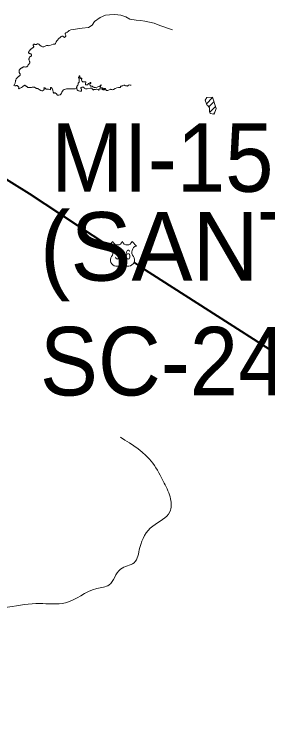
# Model space of a CAD drawing. Extents: x 553962 to 842807, y 8883888 to 9032388.
# Drawn here: x 598511 to 600358, y 8911220 to 8916501 of the extents above; entities that cross this region are included whole.
import ezdxf
from ezdxf.enums import TextEntityAlignment as Align

# ---------------------------------------------------------------- set-up
doc = ezdxf.new("R2010")
doc.units = 0
doc.header["$LTSCALE"] = 200
doc.layers.add('6', color=7, linetype='Continuous', lineweight=13)

msp = doc.modelspace()

# ---------------------------------------------------------------- linework, layer by layer
at = {"layer": '6'}
for p, q in [((599911.6, 8915849.7), (599957.3, 8915895.4)), ((599930.4, 8915826.1), (599967.3, 8915863)), ((599936, 8915789.3), (599977.2, 8915830.5)), ((599963, 8915773.8), (599972, 8915782.8)), ((599197.4, 8914812), (599229.4, 8914844)), ((599369.2, 8914844), (599401.2, 8914812))]:
    msp.add_line(p, q, dxfattribs=at)
at = {"layer": '6', "lineweight": 40}
for points in [[(596588.2, 8916457.2), (598619.5, 8915193.9), (599198.7, 8914813.4)], [(599384.5, 8914691.3), (599431.6, 8914660.4), (600961.1, 8913682.3), (601460.1, 8913331.7), (601690.5, 8912983.4), (601771, 8912890.8), (601830.7, 8912847.9), (601883.5, 8912819.1), (601916.8, 8912809.3)]]:
    msp.add_lwpolyline(points, dxfattribs=at)
at = {"layer": '6'}
for points in [[(599664, 8916389.5), (599573.3, 8916420.2), (599530.2, 8916437.2), (599461.5, 8916451.1), (599431.6, 8916456.9), (599399.5, 8916459.4), (599354, 8916466.4), (599323.1, 8916483.3), (599287.7, 8916495.8), (599244.5, 8916500.6), (599205.7, 8916498.8), (599176.8, 8916494.6), (599135.6, 8916479.4), (599094.3, 8916448.7), (599077.5, 8916423.3), (599051.8, 8916404.7), (599005.2, 8916401.8), (598921.8, 8916388.1), (598911.5, 8916383.7), (598902.3, 8916377.5), (598896.6, 8916370.4)], [(598896.6, 8916370.4), (598896.5, 8916370.3), (598893.5, 8916368.7), (598887.3, 8916366.8), (598882.2, 8916362.8), (598880.8, 8916359.9), (598881.9, 8916356.9), (598884.8, 8916351.1), (598886.9, 8916345), (598886.3, 8916341.8), (598884.8, 8916338.9), (598880.1, 8916334.3), (598877, 8916333.6), (598873.8, 8916334.3), (598868.3, 8916337.8), (598863.6, 8916342.2), (598860.4, 8916342.9), (598857.1, 8916342.3), (598851.2, 8916339.6), (598846.8, 8916334.9), (598841.8, 8916330.9), (598836.5, 8916327.1), (598819.4, 8916307.3), (598815.4, 8916302.1), (598813, 8916296.2), (598811.1, 8916289.8), (598809.4, 8916287.1), (598806.8, 8916285.3), (598793.8, 8916283.8), (598781.7, 8916278.8), (598769.7, 8916273.6), (598763.3, 8916273), (598756.9, 8916274.3)], [(598756.7, 8916274.4), (598751.2, 8916275.1), (598746, 8916273.7), (598736, 8916269.2), (598731.6, 8916266.1), (598726.3, 8916264.3), (598720.8, 8916264.1), (598715.4, 8916265), (598710.1, 8916266.6), (598705.4, 8916269.2), (598697.1, 8916276.4), (598689.5, 8916284.3), (598684.8, 8916287.2), (598682.1, 8916287.3), (598679.5, 8916286.3)], [(599008.9, 8915970.5), (599005.2, 8915971.1), (599001.8, 8915970.8), (598999, 8915968.7), (598996.6, 8915966.3), (598996.6, 8915962.6), (598998.2, 8915958.4), (599000.3, 8915955.5), (599001.3, 8915951.8), (599001.6, 8915948.2), (599001.1, 8915944.2), (599000.3, 8915942.6), (598996.1, 8915942.1), (598992.9, 8915942.1), (598988.2, 8915942.4), (598980.2, 8915944.2), (598973.4, 8915946.6), (598969.4, 8915950.7), (598967.1, 8915956.6), (598965.2, 8915970.8), (598965.5, 8915975.2), (598968.9, 8915978.4), (598971.6, 8915982.3), (598974.5, 8915987), (598975.3, 8915992.3), (598975.3, 8915995.2), (598975.5, 8915998.1), (598976.8, 8916000.4), (598980.5, 8916004.1), (598983.4, 8916008.3), (598983.4, 8916013.8), (598983.2, 8916023.6), (598982.9, 8916029.1), (598982.9, 8916032.5), (598981.6, 8916036.2), (598979, 8916039.9), (598981.8, 8916043.3), (598983.7, 8916049.1), (598985.3, 8916051.4), (598985.5, 8916054.1), (598987.1, 8916053.5), (598987.4, 8916050.1), (598987.7, 8916046.6), (598989.2, 8916043.5), (598993.2, 8916037), (598994.2, 8916034.6), (598996.6, 8916034.9), (598999, 8916036.4), (599001.1, 8916036.7), (599002.9, 8916034.1), (599001.3, 8916030.1), (599001.6, 8916025.9), (599001.6, 8916022), (599003.2, 8916017.2), (599005.3, 8916012.8), (599008.7, 8916010.4), (599011.8, 8916009.8)], [(599084.8, 8915949.4), (599084.9, 8915951), (599083.9, 8915953.7), (599079.6, 8915958), (599076.2, 8915963), (599073.6, 8915964.1), (599070.4, 8915964.2), (599064.2, 8915963), (599040.7, 8915959.1), (599028.6, 8915958.6), (599023.2, 8915961.1), (599019.1, 8915965.5), (599014.9, 8915969.5), (599008.8, 8915970.5), (599002.7, 8915971), (598997.7, 8915967.7), (598996.3, 8915965.3), (598996.7, 8915962.2), (598999.3, 8915956.9), (599001.4, 8915951.3), (599001.3, 8915945.3), (599000.2, 8915942.6), (598997.3, 8915942), (598991.2, 8915942.1), (598979.4, 8915944.4), (598973.7, 8915946.4), (598969.8, 8915950.1), (598967.4, 8915955.4), (598966.2, 8915961.8), (598965.5, 8915968.6), (598965.3, 8915974.9), (598969.6, 8915979.1), (598972.8, 8915984.2), (598975.1, 8915989.6), (598975.3, 8915995.6), (598975.7, 8915998.6), (598977.4, 8916001.1), (598981.7, 8916005.3), (598983.3, 8916007.9), (598983.7, 8916010.8), (598983.3, 8916016.9), (598982.9, 8916028.8), (598982.4, 8916034.8), (598978.9, 8916039.8), (598982.5, 8916044.6), (598983.1, 8916047.6), (598984.6, 8916050.1), (598985.2, 8916053.2), (598985.8, 8916054.1), (598987.3, 8916053.4), (598987.5, 8916047.2), (598993.2, 8916036.7), (598993.7, 8916035.1), (598994.8, 8916034.4), (598997.7, 8916035.6), (599000.4, 8916036.8), (599002.7, 8916035), (599002.3, 8916032.1), (599001.2, 8916029.3), (599001.6, 8916023.2), (599003.1, 8916017.5), (599005.8, 8916012.2), (599008.3, 8916010.6), (599011.3, 8916009.8), (599017.3, 8916009.3), (599029.2, 8916008.2), (599032, 8916006.7), (599032.1, 8916004), (599029.5, 8915998.4), (599028.7, 8915992.5), (599030.6, 8915990.1), (599033.2, 8915988.5), (599038.9, 8915986.9), (599045, 8915987.8), (599047.6, 8915989.5), (599049, 8915992.2), (599049.9, 8915995.1), (599052.1, 8915996.9), (599057.1, 8916000.2), (599062.8, 8916002.2), (599065.4, 8916003.5), (599068.2, 8916003.6), (599068.2, 8916000.4), (599067.4, 8915997.6), (599062.5, 8915994.1), (599062.3, 8915988.1), (599065, 8915982.7), (599069.2, 8915978.6), (599071.7, 8915976.9), (599074.9, 8915976.9), (599077.9, 8915976.9), (599079.8, 8915974.8), (599082.2, 8915973.6), (599085.4, 8915973.6), (599090.5, 8915970.2), (599093, 8915968.8)], [(599093, 8915968.8), (599096, 8915968.4), (599102, 8915968.8), (599113.8, 8915971.1), (599125.2, 8915974.7), (599130.8, 8915973.1), (599134.3, 8915973.4), (599135.2, 8915974), (599134.6, 8915975.3), (599134.3, 8915978.3), (599136.3, 8915980.6), (599138.7, 8915982.3), (599141.3, 8915983.6), (599141.8, 8915985), (599141.2, 8915986.4), (599141.1, 8915987.6), (599142.8, 8915987.7), (599144.3, 8915986.8), (599144.6, 8915985.5), (599142.6, 8915983.1), (599139.9, 8915977.8), (599139.2, 8915971.8), (599139.2, 8915968.8), (599141.3, 8915967), (599147.4, 8915966.3), (599150.5, 8915965.1), (599152.7, 8915963), (599152.8, 8915960), (599154.1, 8915959.1), (599155.8, 8915959.1), (599157.2, 8915961.6), (599159.7, 8915962.2), (599166.6, 8915960.2), (599172.6, 8915960.3), (599175.4, 8915959.6), (599177.1, 8915956.7), (599177, 8915955.3), (599175.6, 8915955.1), (599173.2, 8915956.8), (599167.2, 8915957.4), (599167, 8915955.9), (599168.3, 8915955.1), (599168.7, 8915953.8), (599167.5, 8915952.9), (599165.6, 8915950.8), (599162.7, 8915951.6), (599160.7, 8915953.8), (599159.3, 8915953.6), (599158.3, 8915952.4), (599155.8, 8915950.9), (599153.3, 8915952.5), (599147.8, 8915954.7), (599143.4, 8915958.7), (599137.4, 8915959.2), (599134.3, 8915959.1), (599132, 8915957.4), (599129.5, 8915955.8), (599127.7, 8915953.4), (599127.5, 8915947.2), (599127.1, 8915946.7), (599126.1, 8915947.5), (599123.5, 8915950.7), (599118.3, 8915953.7), (599112.6, 8915955.2), (599106.6, 8915954.9), (599103.8, 8915953.7), (599100.8, 8915953.5), (599094.9, 8915954.2), (599091.9, 8915954.2), (599089.1, 8915953.3), (599087.7, 8915950.6), (599084.9, 8915949.5)], [(599176.8, 8915955.2), (599177.7, 8915952.1), (599179.8, 8915949.5), (599182.3, 8915947.3), (599185.3, 8915946.2), (599191.9, 8915945.7), (599197.9, 8915948.5), (599209.9, 8915953.8), (599212.9, 8915955.1), (599216.1, 8915954.6), (599222.5, 8915953.2), (599228.9, 8915952.1), (599235.1, 8915954.3), (599246.6, 8915960.7), (599258.6, 8915965.9), (599271.5, 8915967.2), (599278, 8915967.5), (599281.5, 8915967.6), (599284.1, 8915969.1), (599286.3, 8915975.3), (599288.3, 8915977.7), (599291.6, 8915977.5), (599294.8, 8915977.3), (599297.7, 8915979), (599303, 8915982.6), (599309.2, 8915984.8), (599312.6, 8915985.5), (599315.2, 8915983.9), (599317.7, 8915981.7), (599320.7, 8915980.5), (599327.2, 8915979.6), (599333.7, 8915979.2), (599336.9, 8915978.5), (599338.4, 8915979), (599339.3, 8915980.4), (599343.9, 8915985), (599346.9, 8915986.2), (599350.2, 8915986.3), (599356.7, 8915984.8), (599363.2, 8915985.6)], [(598679.3, 8915960.3), (598680.9, 8915959.6), (598684.7, 8915957.5), (598691.2, 8915953.3), (598703.5, 8915946.7), (598710, 8915943.5), (598713.4, 8915943.1), (598716.8, 8915944.3), (598723, 8915947.6), (598725.8, 8915949.9), (598727.3, 8915953), (598727.4, 8915960.1), (598726.6, 8915963.4), (598727.6, 8915964.8), (598729.4, 8915965.5), (598732.8, 8915965.5), (598736.1, 8915964.1), (598741.1, 8915959.1), (598743.6, 8915956.6), (598746.7, 8915954.8), (598753.7, 8915954.9), (598760.8, 8915955.2), (598767.5, 8915952.9), (598774, 8915950.1), (598775.1, 8915951.3), (598775, 8915953.1), (598775.4, 8915956.6), (598774.8, 8915960), (598773.3, 8915963.2), (598773.3, 8915966.7), (598776, 8915969), (598779.5, 8915968.9), (598782, 8915966.5), (598785.6, 8915960.4), (598792.2, 8915948), (598795, 8915934.1), (598795.2, 8915930.6), (598796.7, 8915927.7), (598800.2, 8915927.6), (598804.3, 8915928.3), (598807.8, 8915928.6), (598811, 8915927.6), (598816.6, 8915923.1), (598824.8, 8915912), (598825.9, 8915911.7)]]:
    msp.add_lwpolyline(points, dxfattribs=at)
msp.add_lwpolyline([(599968.6, 8915772.5), (599982.2, 8915814.2), (599956.8, 8915897.3), (599915.6, 8915895.7), (599902.2, 8915874.7), (599914.8, 8915841.3), (599922.6, 8915837.8), (599935.3, 8915818.7), (599934.5, 8915793.9), (599939.4, 8915779.5)], close=True, dxfattribs=at)
for centre, radius, start, end in [((599264.3, 8914857.4), 37.4, 200.9593, 339.0407), ((599334.3, 8914857.4), 37.4, 200.9593, 339.0407), ((599185, 8914767.6), 46.1, 317.5721, 74.3689), ((599413.6, 8914767.6), 46.1, 105.6277, 222.4279), ((599255.7, 8914710.6), 44.9, 144.7373, 264.6578), ((599342.9, 8914710.6), 44.9, 275.3422, 35.2627), ((599251.3, 8914547.9), 118, 72.8937, 89.9006), ((599280.4, 8914642.6), 18.9, 357.6934, 72.9296), ((599318.2, 8914642.6), 18.9, 107.0704, 182.3065), ((599347.3, 8914547.9), 118, 90.0994, 107.1063)]:
    msp.add_arc(centre, radius, start, end, dxfattribs=at)
for points in [[(598679.5, 8916286.3), (598678.8, 8916285.7), (598676.5, 8916284.7), (598673.8, 8916283), (598669.9, 8916281.6), (598665.8, 8916281.6), (598661, 8916282.2), (598658.3, 8916283.1), (598654, 8916284.1), (598650, 8916283.7), (598648.7, 8916281.8), (598648, 8916277.7), (598648, 8916275.1), (598649.7, 8916271.8), (598651.9, 8916267.3), (598651.9, 8916263), (598648.3, 8916258.8), (598644, 8916256.1), (598639.5, 8916253.8), (598636.1, 8916251.4), (598631.7, 8916247.3), (598626.6, 8916242.6), (598622.3, 8916238.7), (598618.9, 8916234.5), (598615.1, 8916228.9), (598613.5, 8916224.3), (598612.7, 8916220.8), (598614.4, 8916218.5), (598621, 8916217.1), (598626.8, 8916214.2), (598633, 8916210.8), (598635.1, 8916207.7), (598637.2, 8916203.7), (598636.7, 8916200), (598632.4, 8916196.2), (598628.8, 8916194.5), (598625.1, 8916193.8), (598621.6, 8916187.9), (598619, 8916182.7), (598617.6, 8916180), (598616.8, 8916177.7), (598616.8, 8916174.6), (598617.8, 8916170.6), (598619.8, 8916163.9), (598621.8, 8916158), (598623.8, 8916151), (598622.9, 8916145.1), (598616.7, 8916137.4), (598611.9, 8916132.6), (598609.7, 8916127.3), (598605.8, 8916120.6), (598598.2, 8916118), (598588.6, 8916117.2), (598581.9, 8916118.5), (598576.4, 8916118.5), (598572.5, 8916116.3), (598566.9, 8916112), (598560.8, 8916108.9), (598556.5, 8916105.6), (598551.7, 8916102.2), (598547.7, 8916098.3), (598545.4, 8916092.1), (598545.5, 8916088.6), (598545.5, 8916082.7), (598546.1, 8916078.2), (598549, 8916072.8), (598552.4, 8916067.2), (598554.1, 8916062.7), (598552.4, 8916057.7), (598549.3, 8916053.8), (598543, 8916049.8), (598536.7, 8916044.7), (598530.5, 8916038.6), (598524.2, 8916031), (598521.6, 8916025.1), (598519.9, 8916018.9), (598518.5, 8916009.1), (598515.9, 8915999), (598512, 8915990.6), (598510.7, 8915987.1), (598507, 8915979.5)], [(598515.9, 8915979.5), (598516.1, 8915979.6), (598518.1, 8915980.2), (598522.2, 8915981.3), (598526.3, 8915982.8), (598531.6, 8915982.8), (598534.6, 8915979.2), (598536.3, 8915976.7), (598537.6, 8915975.5)], [(598537.6, 8915975.5), (598538.8, 8915974.2), (598541.8, 8915971.8), (598544.6, 8915968.8), (598543.2, 8915964.3), (598541, 8915961), (598541.6, 8915958.6), (598545.1, 8915959.2), (598551.8, 8915962.7), (598562.2, 8915968), (598577.8, 8915978.9), (598582.3, 8915982.7), (598585.4, 8915984.9), (598588.7, 8915984.2), (598592.3, 8915981.1), (598595.8, 8915977.2), (598600.7, 8915975), (598605.8, 8915971.6), (598609.7, 8915968.4), (598613.4, 8915967.2), (598617.7, 8915966.8), (598623, 8915967.3), (598628.1, 8915968.3), (598636.4, 8915968.8), (598645.4, 8915970), (598654.4, 8915969.8), (598659.8, 8915969.2), (598663.5, 8915966.9), (598667.4, 8915963), (598671, 8915961), (598675, 8915960.6), (598677.9, 8915960.6), (598679.3, 8915960.3)]]:
    msp.add_open_spline(points, degree=3, dxfattribs=at)
for points in [[(598825.9, 8915911.7), (598844.6, 8915914.6), (598861.2, 8915942.1), (598891.6, 8915957.8), (598918, 8915957.8), (598966.1, 8915959.7)], [(596703.8, 8909915.9), (596714.2, 8910009.9), (596839.6, 8910140.6), (597012.1, 8910266), (597195, 8910391.4), (597330.8, 8910501.1), (597419.6, 8910610.8), (597498, 8910741.4), (597492.8, 8910882.5), (597613, 8910960.9), (597759.2, 8911034), (597905.6, 8911185.6), (597895.1, 8911300.5), (597968.2, 8911373.7), (597957.8, 8911425.9), (597853.3, 8911509.5), (597801.1, 8911598.3), (597889.9, 8911729), (598031, 8911870), (598140.7, 8911786.4), (598271.3, 8911875.3), (598354.9, 8911995.4), (598297.4, 8912120.8), (598459.4, 8912178.3), (598694.5, 8912204.4), (598882.6, 8912209.7), (599112.5, 8912314.2), (599201.4, 8912340.3), (599285, 8912455.2), (599384.2, 8912502.3), (599426, 8912612.4), (599520.1, 8912769.3), (599645.5, 8912873.8), (599650.7, 8912967.9), (599603.7, 8913082.9), (599520.1, 8913229.3), (599285, 8913417.5)]]:
    msp.add_spline(points, degree=3, dxfattribs=at)

# ---------------------------------------------------------------- texts
at = {"layer": '6', "width": 0.95}
for s, p in [('MI-1522', (598778.2, 8915207.6)), ('SC-24-X-D-I', (598696.7, 8913722.1))]:
    msp.add_text(s, height=500, dxfattribs=at).set_placement(p)
at = {"layer": '6'}
msp.add_text('(SANTANA DO IPANEMA)', height=500, dxfattribs=at).set_placement((598696.7, 8914559.1))
at = {"layer": '6', "width": 0.75}
msp.add_text('316', height=70, dxfattribs=at).set_placement((599301.3, 8914714.4), align=Align.CENTER)

doc.saveas('drawing.dxf')
